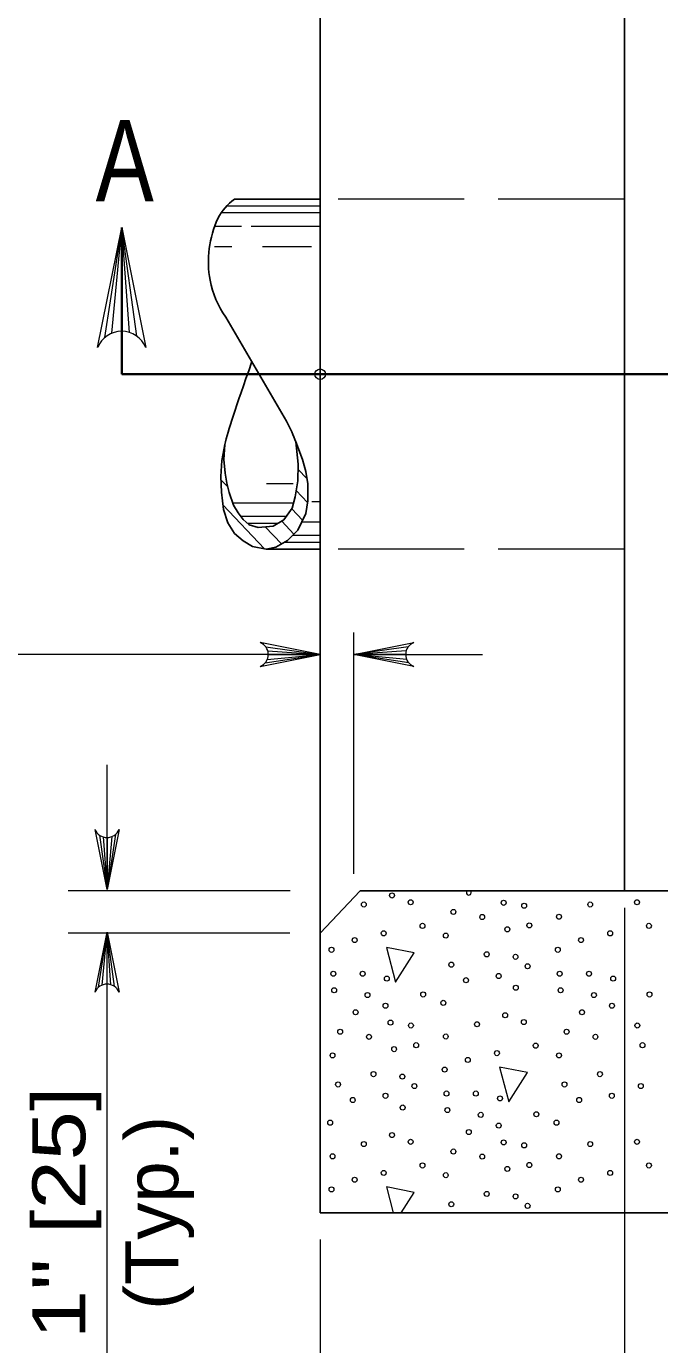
# Model space of a CAD drawing. Extents: x -410.5 to -376.5, y 1617.6 to 1661.6.
# Drawn here: x -406.226 to -404.359, y 1643.026 to 1646.914 of the extents above; entities that cross this region are included whole.
import ezdxf
from ezdxf.enums import TextEntityAlignment as Align

# ---------------------------------------------------------------- set-up
doc = ezdxf.new("R2010")
doc.units = 0
doc.header["$LTSCALE"] = 0.062
doc.header["$PDMODE"] = 32
doc.header["$PDSIZE"] = 0.031
doc.linetypes.add('LONG_DASHED', pattern=[7.5, 6, -1.5])
doc.layers.add('1', color=7, linetype='Continuous', lineweight=13)

msp = doc.modelspace()

# ---------------------------------------------------------------- linework, layer by layer
at = {"layer": '1', "lineweight": 25}
for p, q in [((-404.46308, 1647.41208), (-404.46308, 1644.36383)), ((-405.35992, 1646.404), (-405.61275, 1646.404)), ((-405.45883, 1645.74983), (-405.63808, 1646.05633)), ((-405.35992, 1645.37192), (-405.519, 1645.37192)), ((-405.24192, 1644.36383), (-405.35992, 1644.23892)), ((-405.24192, 1644.36383), (-404.46308, 1644.36383))]:
    msp.add_line(p, q, dxfattribs=at)
at = {"layer": '1'}
for p, q in [((-405.35992, 1646.384), (-405.63517, 1646.384)), ((-405.35992, 1646.364), (-405.65133, 1646.364)), ((-405.99475, 1645.99633), (-405.94517, 1646.32058)), ((-405.974, 1646.00858), (-405.94517, 1646.32058)), ((-405.94517, 1646.01425), (-405.94517, 1646.32058)), ((-405.9225, 1646.011), (-405.94517, 1646.32058)), ((-405.90033, 1646.00008), (-405.94517, 1646.32058)), ((-405.592, 1646.324), (-405.67117, 1646.324)), ((-405.35992, 1646.324), (-405.56383, 1646.324)), ((-404.463, 1646.31075), (-404.46308, 1646.31075)), ((-405.62017, 1646.26408), (-405.67117, 1646.26408)), ((-405.38575, 1646.26408), (-405.52958, 1646.26408)), ((-404.46308, 1646.22567), (-404.463, 1646.22583)), ((-405.4305, 1645.686), (-405.43133, 1645.68692)), ((-405.42742, 1645.6775), (-405.43075, 1645.68117)), ((-405.6435, 1645.63692), (-405.64817, 1645.64192)), ((-405.642, 1645.66358), (-405.64392, 1645.66558)), ((-405.64342, 1645.63483), (-405.6485, 1645.64017)), ((-405.39867, 1645.57925), (-405.4255, 1645.60767)), ((-404.463, 1645.604), (-404.46308, 1645.604)), ((-405.63258, 1645.55558), (-405.65242, 1645.57642)), ((-405.43942, 1645.56467), (-405.51858, 1645.56467)), ((-405.39717, 1645.50983), (-405.43058, 1645.54517)), ((-405.52417, 1645.373), (-405.64658, 1645.5025)), ((-405.43825, 1645.508), (-405.61775, 1645.508)), ((-405.41175, 1645.45742), (-405.44358, 1645.49117)), ((-405.35992, 1645.51183), (-405.38417, 1645.51183)), ((-404.46308, 1645.519), (-404.463, 1645.51917)), ((-405.46008, 1645.468), (-405.59333, 1645.468)), ((-405.48475, 1645.448), (-405.57383, 1645.448)), ((-405.43717, 1645.4165), (-405.47317, 1645.45467)), ((-405.35992, 1645.45183), (-405.41433, 1645.45183)), ((-405.474, 1645.38767), (-405.52167, 1645.438)), ((-405.35992, 1645.41192), (-405.44175, 1645.41192)), ((-405.35992, 1645.39192), (-405.46633, 1645.39192)), ((-405.26083, 1644.41383), (-405.26083, 1645.12567)), ((-405.35992, 1645.06125), (-407.16708, 1645.06125)), ((-405.522, 1645.03642), (-405.35992, 1645.06125)), ((-405.52008, 1645.08367), (-405.35992, 1645.06125)), ((-405.51583, 1645.04683), (-405.35992, 1645.06125)), ((-405.51467, 1645.0725), (-405.35992, 1645.06125)), ((-405.513, 1645.06125), (-405.35992, 1645.06125)), ((-405.10058, 1645.08367), (-405.26083, 1645.06125)), ((-405.106, 1645.0725), (-405.26083, 1645.06125)), ((-405.26083, 1645.06125), (-404.88125, 1645.06125)), ((-405.10767, 1645.06125), (-405.26083, 1645.06125)), ((-405.10483, 1645.04683), (-405.26083, 1645.06125)), ((-405.09867, 1645.03642), (-405.26083, 1645.06125)), ((-404.463, 1644.89733), (-404.46308, 1644.89733)), ((-404.46308, 1644.81233), (-404.463, 1644.8125)), ((-405.98842, 1644.36825), (-405.98842, 1644.73592)), ((-406.01083, 1644.5285), (-405.98842, 1644.36825)), ((-405.99975, 1644.523), (-405.98842, 1644.36825)), ((-405.96358, 1644.53033), (-405.98842, 1644.36825)), ((-405.974, 1644.52425), (-405.98842, 1644.36825)), ((-405.98842, 1644.52142), (-405.98842, 1644.36825)), ((-405.44792, 1644.36383), (-406.10283, 1644.36383)), ((-404.46308, 1644.31375), (-404.46308, 1642.69667)), ((-406.01317, 1644.08), (-405.98842, 1644.24217)), ((-406.00283, 1644.08617), (-405.98842, 1644.24217)), ((-405.98842, 1642.80217), (-405.98842, 1644.24217)), ((-405.98842, 1644.089), (-405.98842, 1644.24217)), ((-405.97708, 1644.08733), (-405.98842, 1644.24217)), ((-405.966, 1644.08192), (-405.98842, 1644.24217)), ((-405.44942, 1644.23892), (-406.10283, 1644.23892)), ((-405.1645, 1643.49058), (-405.14433, 1643.41433)), ((-405.35992, 1643.33558), (-405.35992, 1642.69667))]:
    msp.add_line(p, q, dxfattribs=at)
at = {"layer": '1', "linetype": 'LONG_DASHED'}
for p, q in [((-404.46308, 1646.404), (-405.35992, 1646.404)), ((-404.46308, 1645.37192), (-405.35992, 1645.37192))]:
    msp.add_line(p, q, dxfattribs=at)
at = {"layer": '1', "lineweight": 35}
for q in [(-405.94517, 1646.32058), (-402.19475, 1645.88792)]:
    msp.add_line((-405.94517, 1645.88792), q, dxfattribs=at)
at = {"layer": '1', "lineweight": 25}
msp.add_lwpolyline([(-405.35992, 1643.41425), (-400.73433, 1643.41425), (-400.73433, 1648.3615), (-405.35992, 1648.3615), (-405.35992, 1647.537), (-405.35992, 1644.23892)], close=True, dxfattribs=at)
for points in [[(-404.46308, 1644.36383), (-404.46308, 1644.36375), (-401.63108, 1644.36375), (-401.63108, 1647.41208), (-404.46308, 1647.41208)], [(-405.4315, 1645.68883), (-405.412, 1645.63592), (-405.40233, 1645.60133), (-405.39617, 1645.56442), (-405.39633, 1645.51483), (-405.40267, 1645.47708), (-405.42533, 1645.428), (-405.45633, 1645.3975), (-405.49083, 1645.37825), (-405.519, 1645.37192), (-405.55925, 1645.37967), (-405.58692, 1645.396), (-405.61267, 1645.41833), (-405.63208, 1645.44958), (-405.64492, 1645.48908), (-405.65133, 1645.54033), (-405.65275, 1645.58625), (-405.64975, 1645.63333), (-405.64108, 1645.68075)], [(-405.4315, 1645.68883), (-405.412, 1645.63592), (-405.40233, 1645.60133), (-405.39617, 1645.56442), (-405.39633, 1645.51483), (-405.40267, 1645.47708), (-405.42533, 1645.428), (-405.45633, 1645.3975), (-405.49083, 1645.37825), (-405.519, 1645.37192), (-405.55925, 1645.37967), (-405.58692, 1645.396), (-405.61267, 1645.41833), (-405.63208, 1645.44958), (-405.64492, 1645.48908), (-405.65133, 1645.54033), (-405.65275, 1645.58625), (-405.64975, 1645.63333), (-405.64108, 1645.68075)], [(-405.64108, 1645.68075), (-405.64358, 1645.63608), (-405.63983, 1645.59642), (-405.63542, 1645.56617), (-405.62808, 1645.53892), (-405.61558, 1645.50158), (-405.60167, 1645.479), (-405.58692, 1645.4595), (-405.56933, 1645.444), (-405.54292, 1645.43617), (-405.49883, 1645.44), (-405.46717, 1645.458), (-405.44217, 1645.493), (-405.43342, 1645.52642), (-405.42608, 1645.57392), (-405.42525, 1645.62292), (-405.4315, 1645.68883)], [(-405.64108, 1645.68075), (-405.64358, 1645.63608), (-405.63983, 1645.59642), (-405.63542, 1645.56617), (-405.62808, 1645.53892), (-405.61558, 1645.50158), (-405.60167, 1645.479), (-405.58692, 1645.4595), (-405.56933, 1645.444), (-405.54292, 1645.43617), (-405.49883, 1645.44), (-405.46717, 1645.458), (-405.44217, 1645.493), (-405.43342, 1645.52642), (-405.42608, 1645.57392), (-405.42525, 1645.62292), (-405.4315, 1645.68883)]]:
    msp.add_lwpolyline(points, dxfattribs=at)
at = {"layer": '1'}
for points in [[(-406.016, 1645.96658), (-405.94517, 1646.32058), (-405.87442, 1645.96658)], [(-405.53692, 1645.02583), (-405.35992, 1645.06125), (-405.53692, 1645.09658)], [(-405.08383, 1645.02583), (-405.26083, 1645.06125), (-405.08383, 1645.09658)], [(-405.953, 1644.54525), (-405.98842, 1644.36825), (-406.02383, 1644.54525)], [(-406.02383, 1644.06517), (-405.98842, 1644.24217), (-405.953, 1644.06517)], [(-405.12092, 1643.41433), (-405.0825, 1643.47458), (-405.1645, 1643.49058)]]:
    msp.add_lwpolyline(points, dxfattribs=at)
for points in [[(-405.1645, 1644.19725), (-405.1375, 1644.09483), (-405.0825, 1644.18125)], [(-404.83075, 1643.84383), (-404.80375, 1643.7415), (-404.74883, 1643.828)]]:
    msp.add_lwpolyline(points, close=True, dxfattribs=at)
for centre, radius, start, end in [((-405.94511, 1645.93802), 0.0764, 22.08782, 157.91395), ((-405.55117, 1645.06125), 0.0382, 292.08605, 67.91218), ((-405.0695, 1645.06125), 0.0382, 112.08782, 247.91395), ((-405.98844, 1644.55951), 0.0382, 202.08782, 337.91395), ((-405.98836, 1644.05086), 0.0382, 22.08782, 157.91395)]:
    msp.add_arc(centre, radius, start, end, dxfattribs=at)
at = {"layer": '1', "lineweight": 25}
for centre, major_axis, start_param, end_param in [((-405.51894, 1646.26148), (0, 0.17367), 0.608535, 1.0523476), ((-405.41774, 1646.21986), (0, 0.28786), 1.1112416, 1.7626188), ((-405.44367, 1646.21537), (0, 0.26008), 1.7657992, 2.2285353), ((-405.32341, 1644.2877), (0, -0.00756), 0.4558028, 1.0993283)]:
    msp.add_ellipse(centre, major_axis=major_axis, ratio=0.944543, start_param=start_param, end_param=end_param, dxfattribs=at)
at = {"layer": '1'}
msp.add_ellipse((-404.92182, 1644.35932), major_axis=(0, 0.00756), ratio=0.944543, start_param=0.9500214, end_param=5.3411219, dxfattribs=at)
for centre, major_axis in [((-405.23115, 1644.32382), (0, -0.00756)), ((-405.14821, 1644.35049), (0, -0.00756)), ((-405.09325, 1644.33047), (0, -0.00756)), ((-404.81896, 1644.32888), (0, 0.00756)), ((-404.75861, 1644.32022), (0, -0.00756)), ((-404.56364, 1644.32382), (0, -0.00756)), ((-404.42574, 1644.33047), (0, -0.00756)), ((-404.96709, 1644.30185), (0, 0.00756)), ((-404.88209, 1644.28689), (0, 0.00756)), ((-404.65586, 1644.28777), (0, -0.00756)), ((-405.17257, 1644.23883), (0, -0.00756)), ((-405.05815, 1644.2608), (0, 0.00756)), ((-404.80822, 1644.25061), (0, -0.00756)), ((-404.74331, 1644.2621), (0, -0.00756)), ((-404.50506, 1644.23883), (0, -0.00756)), ((-404.39064, 1644.2608), (0, 0.00756)), ((-405.25824, 1644.21881), (0, -0.00756)), ((-404.98962, 1644.23218), (0, 0.00756)), ((-404.59073, 1644.21881), (0, -0.00756)), ((-405.32665, 1644.19019), (0, -0.00756)), ((-404.86886, 1644.17688), (0, -0.00756)), ((-404.7838, 1644.16952), (0, -0.00756)), ((-404.65915, 1644.19019), (0, -0.00756)), ((-405.32126, 1644.11958), (0, -0.00756)), ((-405.23471, 1644.11958), (0, 0.00756)), ((-404.97338, 1644.14632), (0, -0.00756)), ((-404.74837, 1644.14155), (0, -0.00756)), ((-404.65375, 1644.11958), (0, -0.00756)), ((-404.5672, 1644.11958), (0, 0.00756)), ((-405.16356, 1644.10527), (0, -0.00756)), ((-404.9301, 1644.1005), (0, -0.00756)), ((-404.8337, 1644.11292), (0, -0.00756)), ((-404.49605, 1644.10527), (0, -0.00756)), ((-405.31859, 1644.07093), (0, -0.00756)), ((-405.2203, 1644.05662), (0, 0.00756)), ((-405.05631, 1644.05851), (0, -0.00756)), ((-404.78291, 1644.07824), (0, -0.00756)), ((-404.65108, 1644.07093), (0, -0.00756)), ((-404.55279, 1644.05662), (0, 0.00756)), ((-404.38881, 1644.05851), (0, -0.00756)), ((-405.25551, 1644.00604), (0, 0.00756)), ((-405.16718, 1644.02512), (0, 0.00756)), ((-404.99685, 1644.03371), (0, -0.00756)), ((-404.588, 1644.00604), (0, 0.00756)), ((-404.49967, 1644.02512), (0, 0.00756)), ((-405.15271, 1643.97553), (0, 0.00756)), ((-405.09236, 1643.96687), (0, -0.00756)), ((-404.89739, 1643.97047), (0, -0.00756)), ((-404.81445, 1643.99714), (0, -0.00756)), ((-404.7595, 1643.97712), (0, -0.00756)), ((-404.42485, 1643.96687), (0, -0.00756)), ((-405.30084, 1643.9485), (0, 0.00756)), ((-405.21585, 1643.93354), (0, 0.00756)), ((-404.98962, 1643.93442), (0, -0.00756)), ((-404.63334, 1643.9485), (0, 0.00756)), ((-404.54834, 1643.93354), (0, 0.00756)), ((-405.14198, 1643.89726), (0, -0.00756)), ((-405.07706, 1643.90875), (0, -0.00756)), ((-404.83882, 1643.88548), (0, -0.00756)), ((-404.7244, 1643.90745), (0, 0.00756)), ((-404.40955, 1643.90875), (0, -0.00756)), ((-405.32337, 1643.87883), (0, 0.00756)), ((-404.92448, 1643.86546), (0, -0.00756)), ((-404.65586, 1643.87883), (0, 0.00756)), ((-405.20261, 1643.82353), (0, -0.00756)), ((-405.11756, 1643.81617), (0, -0.00756)), ((-404.9929, 1643.83684), (0, -0.00756)), ((-404.5351, 1643.82353), (0, -0.00756)), ((-405.30713, 1643.79297), (0, -0.00756)), ((-405.08212, 1643.7882), (0, -0.00756)), ((-404.63962, 1643.79297), (0, -0.00756)), ((-404.41462, 1643.7882), (0, -0.00756)), ((-405.26385, 1643.74715), (0, -0.00756)), ((-405.16745, 1643.75957), (0, -0.00756)), ((-404.9875, 1643.76623), (0, -0.00756)), ((-404.90095, 1643.76623), (0, 0.00756)), ((-404.82981, 1643.75192), (0, -0.00756)), ((-404.59634, 1643.74715), (0, -0.00756)), ((-404.49995, 1643.75957), (0, -0.00756)), ((-405.11667, 1643.72489), (0, -0.00756)), ((-404.98483, 1643.71758), (0, -0.00756)), ((-404.88654, 1643.70327), (0, 0.00756)), ((-404.72256, 1643.70516), (0, -0.00756)), ((-405.3306, 1643.68037), (0, -0.00756)), ((-404.92176, 1643.65269), (0, 0.00756)), ((-404.83342, 1643.67177), (0, 0.00756)), ((-404.6631, 1643.68037), (0, -0.00756)), ((-405.23115, 1643.61712), (0, -0.00756)), ((-405.14821, 1643.64379), (0, -0.00756)), ((-405.09325, 1643.62377), (0, -0.00756)), ((-404.81896, 1643.62218), (0, 0.00756)), ((-404.75861, 1643.61352), (0, -0.00756)), ((-404.56364, 1643.61712), (0, -0.00756)), ((-404.42574, 1643.62377), (0, -0.00756)), ((-405.32337, 1643.58107), (0, -0.00756)), ((-404.96709, 1643.59515), (0, 0.00756)), ((-404.88209, 1643.58019), (0, 0.00756)), ((-404.65586, 1643.58107), (0, -0.00756)), ((-405.05815, 1643.5541), (0, 0.00756)), ((-404.80822, 1643.54391), (0, -0.00756)), ((-404.74331, 1643.5554), (0, -0.00756)), ((-404.39064, 1643.5541), (0, 0.00756)), ((-405.25824, 1643.51211), (0, -0.00756)), ((-405.17257, 1643.53213), (0, -0.00756)), ((-404.98962, 1643.52548), (0, 0.00756)), ((-404.59073, 1643.51211), (0, -0.00756)), ((-404.50506, 1643.53213), (0, -0.00756)), ((-405.32665, 1643.48349), (0, -0.00756)), ((-404.86886, 1643.47018), (0, -0.00756)), ((-404.7838, 1643.46282), (0, -0.00756)), ((-404.65915, 1643.48349), (0, -0.00756)), ((-404.97338, 1643.43962), (0, -0.00756)), ((-404.74837, 1643.43485), (0, -0.00756))]:
    msp.add_ellipse(centre, major_axis=major_axis, ratio=0.944543, dxfattribs=at)
at = {"layer": '1', "lineweight": 25}
for points in [[(-405.64108, 1645.68075), (-405.631, 1645.72192), (-405.60992, 1645.78817), (-405.56208, 1645.92267)], [(-405.45883, 1645.74983), (-405.44808, 1645.72733), (-405.43908, 1645.70708), (-405.4315, 1645.68883)]]:
    msp.add_open_spline(points, degree=3, dxfattribs=at)
at = {"layer": '1'}
msp.add_point((-405.35992, 1645.88792), dxfattribs=at)

# ---------------------------------------------------------------- texts
at = {"layer": '1', "width": 0.8}
msp.add_text('A', height=0.24, dxfattribs=at).set_placement((-405.93625, 1646.39817), align=Align.CENTER)
at = {"layer": '1'}
for s, width, p in [('1" [25]', 1.25, (-406.05258, 1643.41421)), ('(Typ.)', 1.05, (-405.77858, 1643.41421))]:
    msp.add_text(s, height=0.156, rotation=90, dxfattribs=dict(at, width=width)).set_placement(p, align=Align.CENTER)

doc.saveas('drawing.dxf')
